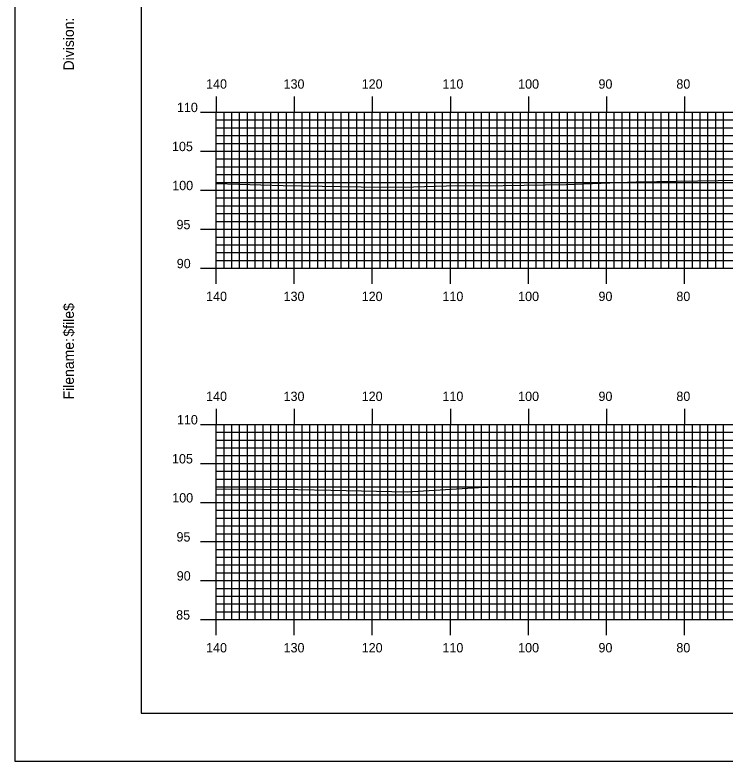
# Model space of a CAD drawing. Extents: x 1775170 to 1775514, y 442591 to 442811.
# Drawn here: x 1775170.4 to 1775261.4, y 442590.5 to 442686.1 of the extents above; entities that cross this region are included whole.
import ezdxf

# ---------------------------------------------------------------- set-up
doc = ezdxf.new("R2010")
doc.units = 0
for name, color, linetype in [('BORDER', 7, 'Continuous'), ('H_V ANNOTATION', 7, 'Continuous'), ('MAJOR', 7, 'Continuous'), ('MINOR', 7, 'Continuous'), ('PLOT BOUNDARY', 7, 'Continuous'), ('S_Roadway_Centerline', 7, 'Continuous')]:
    doc.layers.add(name, color=color, linetype=linetype)

msp = doc.modelspace()

# ---------------------------------------------------------------- linework, layer by layer
at = {"layer": 'BORDER'}
msp.add_lwpolyline([(1775186.598, 442596.665), (1775506.598, 442596.665), (1775506.598, 442806.665), (1775186.598, 442806.665)], close=True, dxfattribs=at)
at = {"layer": 'MAJOR'}
for p, q in [((1775196.198, 442675.669), (1775196.198, 442673.665)), ((1775206.198, 442675.669), (1775206.198, 442673.665)), ((1775216.198, 442675.669), (1775216.198, 442673.665)), ((1775226.198, 442675.669), (1775226.198, 442673.665)), ((1775236.198, 442675.669), (1775236.198, 442673.665)), ((1775246.198, 442675.669), (1775246.198, 442673.665)), ((1775256.198, 442675.669), (1775256.198, 442673.665)), ((1775194.194, 442673.665), (1775196.198, 442673.665)), ((1775196.198, 442673.665), (1775476.198, 442673.665)), ((1775196.198, 442653.665), (1775196.198, 442673.665)), ((1775196.198, 442653.665), (1775196.198, 442673.665)), ((1775196.198, 442673.665), (1775476.198, 442673.665)), ((1775206.198, 442653.665), (1775206.198, 442673.665)), ((1775216.198, 442653.665), (1775216.198, 442673.665)), ((1775226.198, 442653.665), (1775226.198, 442673.665)), ((1775236.198, 442653.665), (1775236.198, 442673.665)), ((1775246.198, 442653.665), (1775246.198, 442673.665)), ((1775256.198, 442653.665), (1775256.198, 442673.665)), ((1775194.194, 442668.665), (1775196.198, 442668.665)), ((1775196.198, 442668.665), (1775476.198, 442668.665)), ((1775194.194, 442663.665), (1775196.198, 442663.665)), ((1775196.198, 442663.665), (1775476.198, 442663.665)), ((1775194.194, 442658.665), (1775196.198, 442658.665)), ((1775196.198, 442658.665), (1775476.198, 442658.665)), ((1775194.194, 442653.665), (1775196.198, 442653.665)), ((1775196.198, 442653.665), (1775476.198, 442653.665)), ((1775196.198, 442653.665), (1775476.198, 442653.665)), ((1775196.198, 442651.661), (1775196.198, 442653.665)), ((1775206.198, 442651.661), (1775206.198, 442653.665)), ((1775216.198, 442651.661), (1775216.198, 442653.665)), ((1775226.198, 442651.661), (1775226.198, 442653.665)), ((1775236.198, 442651.661), (1775236.198, 442653.665)), ((1775246.198, 442651.661), (1775246.198, 442653.665)), ((1775256.198, 442651.661), (1775256.198, 442653.665)), ((1775196.198, 442635.669), (1775196.198, 442633.665)), ((1775206.198, 442635.669), (1775206.198, 442633.665)), ((1775216.198, 442635.669), (1775216.198, 442633.665)), ((1775226.198, 442635.669), (1775226.198, 442633.665)), ((1775236.198, 442635.669), (1775236.198, 442633.665)), ((1775246.198, 442635.669), (1775246.198, 442633.665)), ((1775256.198, 442635.669), (1775256.198, 442633.665)), ((1775194.194, 442633.665), (1775196.198, 442633.665)), ((1775196.198, 442633.665), (1775476.198, 442633.665)), ((1775196.198, 442608.665), (1775196.198, 442633.665)), ((1775196.198, 442608.665), (1775196.198, 442633.665)), ((1775196.198, 442633.665), (1775476.198, 442633.665)), ((1775206.198, 442608.665), (1775206.198, 442633.665)), ((1775216.198, 442608.665), (1775216.198, 442633.665)), ((1775226.198, 442608.665), (1775226.198, 442633.665)), ((1775236.198, 442608.665), (1775236.198, 442633.665)), ((1775246.198, 442608.665), (1775246.198, 442633.665)), ((1775256.198, 442608.665), (1775256.198, 442633.665)), ((1775194.194, 442628.665), (1775196.198, 442628.665)), ((1775196.198, 442628.665), (1775476.198, 442628.665)), ((1775194.194, 442623.665), (1775196.198, 442623.665)), ((1775196.198, 442623.665), (1775476.198, 442623.665)), ((1775194.194, 442618.665), (1775196.198, 442618.665)), ((1775196.198, 442618.665), (1775476.198, 442618.665)), ((1775194.194, 442613.665), (1775196.198, 442613.665)), ((1775196.198, 442613.665), (1775476.198, 442613.665)), ((1775194.194, 442608.665), (1775196.198, 442608.665)), ((1775196.198, 442608.665), (1775476.198, 442608.665)), ((1775196.198, 442608.665), (1775476.198, 442608.665)), ((1775196.198, 442606.661), (1775196.198, 442608.665)), ((1775206.198, 442606.661), (1775206.198, 442608.665)), ((1775216.198, 442606.661), (1775216.198, 442608.665)), ((1775226.198, 442606.661), (1775226.198, 442608.665)), ((1775236.198, 442606.661), (1775236.198, 442608.665)), ((1775246.198, 442606.661), (1775246.198, 442608.665)), ((1775256.198, 442606.661), (1775256.198, 442608.665))]:
    msp.add_line(p, q, dxfattribs=at)
at = {"layer": 'MINOR'}
for p, q in [((1775197.198, 442653.665), (1775197.198, 442673.665)), ((1775198.198, 442653.665), (1775198.198, 442673.665)), ((1775199.198, 442653.665), (1775199.198, 442673.665)), ((1775200.198, 442653.665), (1775200.198, 442673.665)), ((1775201.198, 442653.665), (1775201.198, 442673.665)), ((1775202.198, 442653.665), (1775202.198, 442673.665)), ((1775203.198, 442653.665), (1775203.198, 442673.665)), ((1775204.198, 442653.665), (1775204.198, 442673.665)), ((1775205.198, 442653.665), (1775205.198, 442673.665)), ((1775207.198, 442653.665), (1775207.198, 442673.665)), ((1775208.198, 442653.665), (1775208.198, 442673.665)), ((1775209.198, 442653.665), (1775209.198, 442673.665)), ((1775210.198, 442653.665), (1775210.198, 442673.665)), ((1775211.198, 442653.665), (1775211.198, 442673.665)), ((1775212.198, 442653.665), (1775212.198, 442673.665)), ((1775213.198, 442653.665), (1775213.198, 442673.665)), ((1775214.198, 442653.665), (1775214.198, 442673.665)), ((1775215.198, 442653.665), (1775215.198, 442673.665)), ((1775217.198, 442653.665), (1775217.198, 442673.665)), ((1775218.198, 442653.665), (1775218.198, 442673.665)), ((1775219.198, 442653.665), (1775219.198, 442673.665)), ((1775220.198, 442653.665), (1775220.198, 442673.665)), ((1775221.198, 442653.665), (1775221.198, 442673.665)), ((1775222.198, 442653.665), (1775222.198, 442673.665)), ((1775223.198, 442653.665), (1775223.198, 442673.665)), ((1775224.198, 442653.665), (1775224.198, 442673.665)), ((1775225.198, 442653.665), (1775225.198, 442673.665)), ((1775227.198, 442653.665), (1775227.198, 442673.665)), ((1775228.198, 442653.665), (1775228.198, 442673.665)), ((1775229.198, 442653.665), (1775229.198, 442673.665)), ((1775230.198, 442653.665), (1775230.198, 442673.665)), ((1775231.198, 442653.665), (1775231.198, 442673.665)), ((1775232.198, 442653.665), (1775232.198, 442673.665)), ((1775233.198, 442653.665), (1775233.198, 442673.665)), ((1775234.198, 442653.665), (1775234.198, 442673.665)), ((1775235.198, 442653.665), (1775235.198, 442673.665)), ((1775237.198, 442653.665), (1775237.198, 442673.665)), ((1775238.198, 442653.665), (1775238.198, 442673.665)), ((1775239.198, 442653.665), (1775239.198, 442673.665)), ((1775240.198, 442653.665), (1775240.198, 442673.665)), ((1775241.198, 442653.665), (1775241.198, 442673.665)), ((1775242.198, 442653.665), (1775242.198, 442673.665)), ((1775243.198, 442653.665), (1775243.198, 442673.665)), ((1775244.198, 442653.665), (1775244.198, 442673.665)), ((1775245.198, 442653.665), (1775245.198, 442673.665)), ((1775247.198, 442653.665), (1775247.198, 442673.665)), ((1775248.198, 442653.665), (1775248.198, 442673.665)), ((1775249.198, 442653.665), (1775249.198, 442673.665)), ((1775250.198, 442653.665), (1775250.198, 442673.665)), ((1775251.198, 442653.665), (1775251.198, 442673.665)), ((1775252.198, 442653.665), (1775252.198, 442673.665)), ((1775253.198, 442653.665), (1775253.198, 442673.665)), ((1775254.198, 442653.665), (1775254.198, 442673.665)), ((1775255.198, 442653.665), (1775255.198, 442673.665)), ((1775257.198, 442653.665), (1775257.198, 442673.665)), ((1775258.198, 442653.665), (1775258.198, 442673.665)), ((1775259.198, 442653.665), (1775259.198, 442673.665)), ((1775260.198, 442653.665), (1775260.198, 442673.665)), ((1775261.198, 442653.665), (1775261.198, 442673.665)), ((1775196.198, 442672.665), (1775476.198, 442672.665)), ((1775196.198, 442672.665), (1775198.202, 442672.665)), ((1775196.198, 442671.665), (1775476.198, 442671.665)), ((1775196.198, 442671.665), (1775198.202, 442671.665)), ((1775196.198, 442670.665), (1775476.198, 442670.665)), ((1775196.198, 442670.665), (1775198.202, 442670.665)), ((1775196.198, 442669.665), (1775476.198, 442669.665)), ((1775196.198, 442669.665), (1775198.202, 442669.665)), ((1775196.198, 442667.665), (1775476.198, 442667.665)), ((1775196.198, 442667.665), (1775198.202, 442667.665)), ((1775196.198, 442666.665), (1775476.198, 442666.665)), ((1775196.198, 442666.665), (1775198.202, 442666.665)), ((1775196.198, 442665.665), (1775476.198, 442665.665)), ((1775196.198, 442665.665), (1775198.202, 442665.665)), ((1775196.198, 442664.665), (1775476.198, 442664.665)), ((1775196.198, 442664.665), (1775198.202, 442664.665)), ((1775196.198, 442662.665), (1775476.198, 442662.665)), ((1775196.198, 442662.665), (1775198.202, 442662.665)), ((1775196.198, 442661.665), (1775476.198, 442661.665)), ((1775196.198, 442661.665), (1775198.202, 442661.665)), ((1775196.198, 442660.665), (1775476.198, 442660.665)), ((1775196.198, 442660.665), (1775198.202, 442660.665)), ((1775196.198, 442659.665), (1775476.198, 442659.665)), ((1775196.198, 442659.665), (1775198.202, 442659.665)), ((1775196.198, 442657.665), (1775476.198, 442657.665)), ((1775196.198, 442657.665), (1775198.202, 442657.665)), ((1775196.198, 442656.665), (1775476.198, 442656.665)), ((1775196.198, 442656.665), (1775198.202, 442656.665)), ((1775196.198, 442655.665), (1775476.198, 442655.665)), ((1775196.198, 442655.665), (1775198.202, 442655.665)), ((1775196.198, 442654.665), (1775476.198, 442654.665)), ((1775196.198, 442654.665), (1775198.202, 442654.665)), ((1775197.198, 442608.665), (1775197.198, 442633.665)), ((1775198.198, 442608.665), (1775198.198, 442633.665)), ((1775199.198, 442608.665), (1775199.198, 442633.665)), ((1775200.198, 442608.665), (1775200.198, 442633.665)), ((1775201.198, 442608.665), (1775201.198, 442633.665)), ((1775202.198, 442608.665), (1775202.198, 442633.665)), ((1775203.198, 442608.665), (1775203.198, 442633.665)), ((1775204.198, 442608.665), (1775204.198, 442633.665)), ((1775205.198, 442608.665), (1775205.198, 442633.665)), ((1775207.198, 442608.665), (1775207.198, 442633.665)), ((1775208.198, 442608.665), (1775208.198, 442633.665)), ((1775209.198, 442608.665), (1775209.198, 442633.665)), ((1775210.198, 442608.665), (1775210.198, 442633.665)), ((1775211.198, 442608.665), (1775211.198, 442633.665)), ((1775212.198, 442608.665), (1775212.198, 442633.665)), ((1775213.198, 442608.665), (1775213.198, 442633.665)), ((1775214.198, 442608.665), (1775214.198, 442633.665)), ((1775215.198, 442608.665), (1775215.198, 442633.665)), ((1775217.198, 442608.665), (1775217.198, 442633.665)), ((1775218.198, 442608.665), (1775218.198, 442633.665)), ((1775219.198, 442608.665), (1775219.198, 442633.665)), ((1775220.198, 442608.665), (1775220.198, 442633.665)), ((1775221.198, 442608.665), (1775221.198, 442633.665)), ((1775222.198, 442608.665), (1775222.198, 442633.665)), ((1775223.198, 442608.665), (1775223.198, 442633.665)), ((1775224.198, 442608.665), (1775224.198, 442633.665)), ((1775225.198, 442608.665), (1775225.198, 442633.665)), ((1775227.198, 442608.665), (1775227.198, 442633.665)), ((1775228.198, 442608.665), (1775228.198, 442633.665)), ((1775229.198, 442608.665), (1775229.198, 442633.665)), ((1775230.198, 442608.665), (1775230.198, 442633.665)), ((1775231.198, 442608.665), (1775231.198, 442633.665)), ((1775232.198, 442608.665), (1775232.198, 442633.665)), ((1775233.198, 442608.665), (1775233.198, 442633.665)), ((1775234.198, 442608.665), (1775234.198, 442633.665)), ((1775235.198, 442608.665), (1775235.198, 442633.665)), ((1775237.198, 442608.665), (1775237.198, 442633.665)), ((1775238.198, 442608.665), (1775238.198, 442633.665)), ((1775239.198, 442608.665), (1775239.198, 442633.665)), ((1775240.198, 442608.665), (1775240.198, 442633.665)), ((1775241.198, 442608.665), (1775241.198, 442633.665)), ((1775242.198, 442608.665), (1775242.198, 442633.665)), ((1775243.198, 442608.665), (1775243.198, 442633.665)), ((1775244.198, 442608.665), (1775244.198, 442633.665)), ((1775245.198, 442608.665), (1775245.198, 442633.665)), ((1775247.198, 442608.665), (1775247.198, 442633.665)), ((1775248.198, 442608.665), (1775248.198, 442633.665)), ((1775249.198, 442608.665), (1775249.198, 442633.665)), ((1775250.198, 442608.665), (1775250.198, 442633.665)), ((1775251.198, 442608.665), (1775251.198, 442633.665)), ((1775252.198, 442608.665), (1775252.198, 442633.665)), ((1775253.198, 442608.665), (1775253.198, 442633.665)), ((1775254.198, 442608.665), (1775254.198, 442633.665)), ((1775255.198, 442608.665), (1775255.198, 442633.665)), ((1775257.198, 442608.665), (1775257.198, 442633.665)), ((1775258.198, 442608.665), (1775258.198, 442633.665)), ((1775259.198, 442608.665), (1775259.198, 442633.665)), ((1775260.198, 442608.665), (1775260.198, 442633.665)), ((1775261.198, 442608.665), (1775261.198, 442633.665)), ((1775196.198, 442632.665), (1775476.198, 442632.665)), ((1775196.198, 442632.665), (1775198.202, 442632.665)), ((1775196.198, 442631.665), (1775476.198, 442631.665)), ((1775196.198, 442631.665), (1775198.202, 442631.665)), ((1775196.198, 442630.665), (1775476.198, 442630.665)), ((1775196.198, 442630.665), (1775198.202, 442630.665)), ((1775196.198, 442629.665), (1775476.198, 442629.665)), ((1775196.198, 442629.665), (1775198.202, 442629.665)), ((1775196.198, 442627.665), (1775476.198, 442627.665)), ((1775196.198, 442627.665), (1775198.202, 442627.665)), ((1775196.198, 442626.665), (1775476.198, 442626.665)), ((1775196.198, 442626.665), (1775198.202, 442626.665)), ((1775196.198, 442625.665), (1775476.198, 442625.665)), ((1775196.198, 442625.665), (1775198.202, 442625.665)), ((1775196.198, 442624.665), (1775476.198, 442624.665)), ((1775196.198, 442624.665), (1775198.202, 442624.665)), ((1775196.198, 442622.665), (1775476.198, 442622.665)), ((1775196.198, 442622.665), (1775198.202, 442622.665)), ((1775196.198, 442621.665), (1775476.198, 442621.665)), ((1775196.198, 442621.665), (1775198.202, 442621.665)), ((1775196.198, 442620.665), (1775476.198, 442620.665)), ((1775196.198, 442620.665), (1775198.202, 442620.665)), ((1775196.198, 442619.665), (1775476.198, 442619.665)), ((1775196.198, 442619.665), (1775198.202, 442619.665)), ((1775196.198, 442617.665), (1775476.198, 442617.665)), ((1775196.198, 442617.665), (1775198.202, 442617.665)), ((1775196.198, 442616.665), (1775476.198, 442616.665)), ((1775196.198, 442616.665), (1775198.202, 442616.665)), ((1775196.198, 442615.665), (1775476.198, 442615.665)), ((1775196.198, 442615.665), (1775198.202, 442615.665)), ((1775196.198, 442614.665), (1775476.198, 442614.665)), ((1775196.198, 442614.665), (1775198.202, 442614.665)), ((1775196.198, 442612.665), (1775476.198, 442612.665)), ((1775196.198, 442612.665), (1775198.202, 442612.665)), ((1775196.198, 442611.665), (1775476.198, 442611.665)), ((1775196.198, 442611.665), (1775198.202, 442611.665)), ((1775196.198, 442610.665), (1775476.198, 442610.665)), ((1775196.198, 442610.665), (1775198.202, 442610.665)), ((1775196.198, 442609.665), (1775476.198, 442609.665)), ((1775196.198, 442609.665), (1775198.202, 442609.665))]:
    msp.add_line(p, q, dxfattribs=at)
at = {"layer": 'PLOT BOUNDARY'}
msp.add_lwpolyline([(1775170.412, 442590.547), (1775510.412, 442590.547), (1775510.412, 442810.547), (1775170.412, 442810.547)], close=True, dxfattribs=at)
at = {"layer": 'S_Roadway_Centerline'}
for points in [[(1775196.198, 442664.528), (1775204.776, 442664.259), (1775217.248, 442664.049), (1775221.487, 442664.095), (1775225.698, 442664.209), (1775232.967, 442664.256), (1775241.035, 442664.397), (1775249.997, 442664.756), (1775263.15, 442664.958)], [(1775196.198, 442625.378), (1775197.401, 442625.425), (1775206.641, 442625.345), (1775210.888, 442625.257), (1775220.644, 442625.047), (1775229.795, 442625.607), (1775234.66, 442625.776), (1775251.533, 442625.682), (1775253.83, 442625.738), (1775257.75, 442625.735), (1775261.353, 442625.631), (1775275.145, 442625.513)]]:
    msp.add_lwpolyline(points, dxfattribs=at)

# ---------------------------------------------------------------- texts
at = {"layer": 'BORDER'}
for s, p in [('Division:', (1775177.968, 442678.997)), ('$file$', (1775177.968, 442644.916)), ('Filename:', (1775177.968, 442636.862))]:
    msp.add_text(s, height=1.3392, rotation=90, dxfattribs=at).set_placement(p)
at = {"layer": 'H_V ANNOTATION'}
for s, p in [('140', (1775194.903, 442676.665)), ('130', (1775204.828, 442676.665)), ('120', (1775214.839, 442676.665)), ('110', (1775225.182, 442676.665)), ('100', (1775234.882, 442676.665)), ('90', (1775245.171, 442676.665)), ('80', (1775255.149, 442676.665)), ('110', (1775191.165, 442673.665)), ('105', (1775190.533, 442668.665)), ('100', (1775190.565, 442663.665)), ('95', (1775191.111, 442658.665)), ('90', (1775191.143, 442653.665)), ('140', (1775194.903, 442649.465)), ('130', (1775204.828, 442649.465)), ('120', (1775214.839, 442649.465)), ('110', (1775225.182, 442649.465)), ('100', (1775234.882, 442649.465)), ('90', (1775245.171, 442649.465)), ('80', (1775255.149, 442649.465)), ('140', (1775194.903, 442636.665)), ('130', (1775204.828, 442636.665)), ('120', (1775214.839, 442636.665)), ('110', (1775225.182, 442636.665)), ('100', (1775234.882, 442636.665)), ('90', (1775245.171, 442636.665)), ('80', (1775255.149, 442636.665)), ('110', (1775191.165, 442633.665)), ('105', (1775190.533, 442628.665)), ('100', (1775190.565, 442623.665)), ('95', (1775191.111, 442618.665)), ('90', (1775191.143, 442613.665)), ('85', (1775191.068, 442608.665)), ('140', (1775194.903, 442604.465)), ('130', (1775204.828, 442604.465)), ('120', (1775214.839, 442604.465)), ('110', (1775225.182, 442604.465)), ('100', (1775234.882, 442604.465)), ('90', (1775245.171, 442604.465)), ('80', (1775255.149, 442604.465))]:
    msp.add_text(s, height=1.2, dxfattribs=at).set_placement(p)
at = {"layer": 'MAJOR'}
for p in [(1775196.189, 442653.665), (1775196.189, 442608.665)]:
    msp.add_text('-', height=0.012, dxfattribs=at).set_placement(p)

doc.saveas('drawing.dxf')
